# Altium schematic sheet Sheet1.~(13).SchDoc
size A4; SheetNumber: 1; SheetTotal: 1
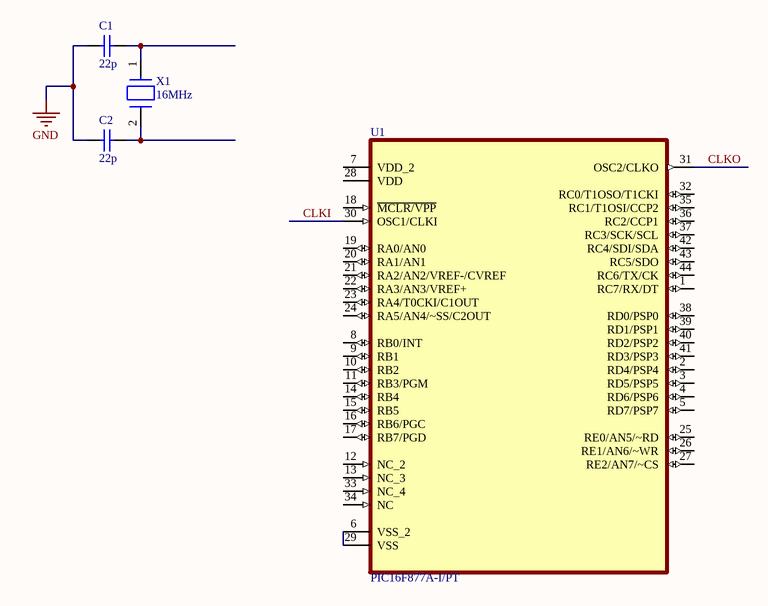
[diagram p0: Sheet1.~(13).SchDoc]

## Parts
C1  22p  [CAPC2013X94X50LL25T25]
C2  22p  [CAPC2013X94X50LL25T25]
U1  PIC16F877A-I/PT  [TQFP-44]
X1  16MHz  [FP-ABM7-MFG]

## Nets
GND: C1.1 C2.1
CLKI: U1.30(OSC1/CLKI)
CLKO: U1.31(OSC2/CLKO)
NetC1_2: C1.2 X1.1
NetC2_2: C2.2 X1.2
NetU1_6: U1.6(VSS_2) U1.29(VSS)

Not connected (* = marked no-connect by the designer): U1 1(RC7/RX/DT) 2(RD4/PSP4) 3(RD5/PSP5) 4(RD6/PSP6) 5(RD7/PSP7) 7(VDD_2) 8(RB0/INT) 9(RB1) 10(RB2) 11(RB3/PGM) 12(NC_2) 13(NC_3) 14(RB4) 15(RB5) 16(RB6/PGC) 17(RB7/PGD) 18(~{MCLR/VPP}) 19(RA0/AN0) 20(RA1/AN1) 21(RA2/AN2/VREF-/CVREF) 22(RA3/AN3/VREF+) 23(RA4/T0CKI/C1OUT) 24(RA5/AN4/~SS/C2OUT) 25(RE0/AN5/~RD) 26(RE1/AN6/~WR) 27(RE2/AN7/~CS) 28(VDD) 32(RC0/T1OSO/T1CKI) 33(NC_4) 34(NC) 35(RC1/T1OSI/CCP2) 36(RC2/CCP1) 37(RC3/SCK/SCL) 38(RD0/PSP0) 39(RD1/PSP1) 40(RD2/PSP2) 41(RD3/PSP3) 42(RC4/SDI/SDA) 43(RC5/SDO) 44(RC6/TX/CK)

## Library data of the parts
C1 C2 = LD051C104KAB2A: Cap Ceramic 0.1uF 100V X7R 10% SMD 0805 125°C Embossed T/R; Manufacturer: Kyocera AVX; Value: 100nF
U1 = PIC16F877A-I/PT: PIC16F877A Microcontroller IC 8-Bit 20MHz 14KB _8K x 14_ FLASH 44-TQFP _10x10_; MF: Microchip
X1 = ABM7-16.000MHZ-4-T: Crystal 16MHz ±30ppm (Tol) ±50ppm (Stability) 18pF FUND 50Ohm 2-Pin Mini-CSMD T/R; Manufacturer: Abracon; ESR (Equivalent Series Resistance): 50R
